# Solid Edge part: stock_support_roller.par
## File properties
Title: Stock support roller
Author: Abhinav Rai
Template: Normal.par
Last saved by: Rajat Kamboj
Revision: 15
Application: Solid Edge
Accuracy: 0.99
Material: aluminum
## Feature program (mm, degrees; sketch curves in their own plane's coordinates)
sketch for "unnamed RevolvedProtrusion 1" plane through (0, 0, 0) normal (0, -1, 0) x-axis (1, 0, 0)
  line (60, 0) -> (60, 18.669)
  line (60, 18.669) -> (15.55, 18.669)
  line (15.55, 18.669) -> (15.55, 92.075)
  line (15.55, 92.075) -> (-2.2388, 92.075)
  line (-2.2388, 92.075) -> (-111.45, 29.0219)
  line (-220.6612, 92.075) -> (-111.45, 29.0219)
  line (-238.45, 92.075) -> (-220.6612, 92.075)
  line (-238.45, 18.669) -> (-238.45, 92.075)
  line (-282.9, 18.669) -> (-238.45, 18.669)
  line (-282.9, 0) -> (-282.9, 18.669)
revolve "unnamed RevolvedProtrusion 1" add full turn 360 deg about sketch line (-282.9, 0) -> (60, 0)
chamfer "unnamed Chamfer 1"
fillet "Round_1" radius 1.5748
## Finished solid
Body 1: solid body, 14 faces, 13 edges, 0 vertices.
  Faces by surface: cone 4, cylinder 4, plane 4, torus 2
  Edges by curve: circle 13
Bounding box of the edges (mm; curved faces can reach further): 342.900 x 184.150 x 184.150, from (-282.9, -92.075, -92.075) to (60, 92.075, 92.075).
Cylindrical faces by radius (mm): R18.669 x2, R92.075 x2
Conical faces (half-angle, radius in mm at the cone's reference point): 30 deg R29.0219 x1, 30 deg R92.075 x1, 45 deg R17.0942 x1, 45 deg R18.669 x1
Toroidal faces (ring radius, tube radius in mm): R20.2438 r1.5748 x2
Planar faces by outward normal: +x 2, -x 2
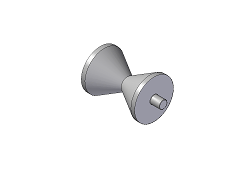
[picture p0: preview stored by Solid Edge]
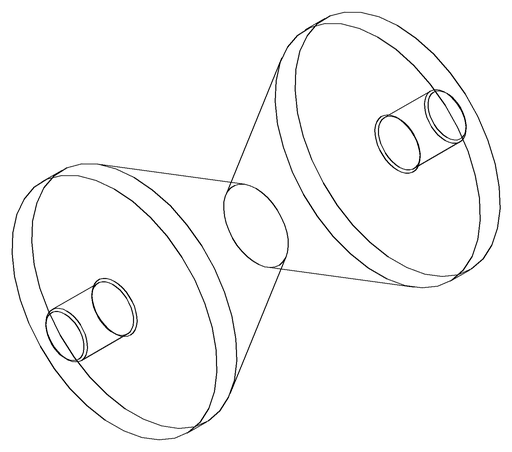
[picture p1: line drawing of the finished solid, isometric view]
